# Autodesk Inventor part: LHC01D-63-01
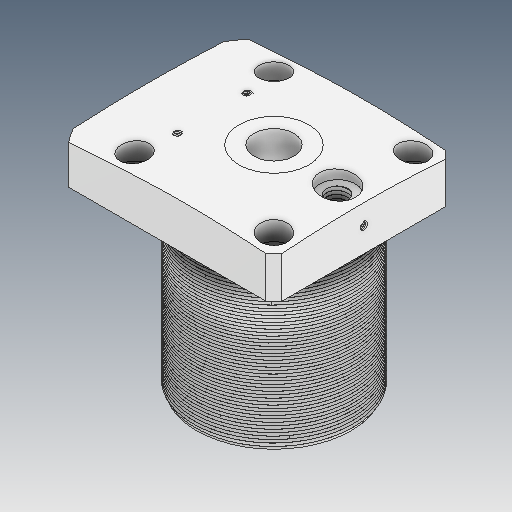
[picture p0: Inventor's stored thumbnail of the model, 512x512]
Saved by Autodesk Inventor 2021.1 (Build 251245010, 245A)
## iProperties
Created: 2021-06
Part Number: LHC01D-63-01
Material: Ogólny
Document SubType Name: Modeling
Designer: user
Density: 1 g/cm^3
Appearance: Domyślna
Author: user
Revision Number: ÈÎºÎ
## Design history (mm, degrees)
feature "ÊäÈë1"
feature "ÊäÈë2"
feature "ÊäÈë3"
node "Bryła1"
node "Bryła2"
node "Bryła3"
